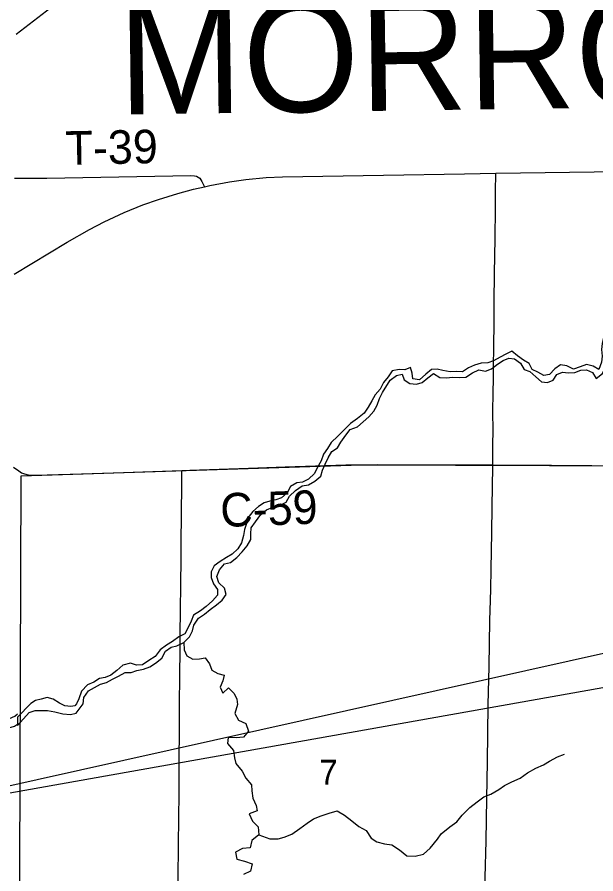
# Model space of a CAD drawing. Extents: x 0 to 45.9, y 0 to 22.
# Drawn here: x 5.48 to 6.459, y 18.033 to 19.483 of the extents above; entities that cross this region are included whole.
import ezdxf

# ---------------------------------------------------------------- set-up
doc = ezdxf.new("R2010")
doc.units = 0
for name, color, linetype in [('GM_X_County_Road', 7, 'Continuous'), ('GM_X_County_Road_Text', 7, 'Continuous'), ('GM_X_County_Text', 7, 'Continuous'), ('GM_X_Minor_River', 7, 'Continuous'), ('GM_X_Rail_Line', 7, 'Continuous'), ('GM_X_Section', 7, 'Continuous'), ('GM_X_Section_Text', 7, 'Continuous'), ('GM_X_State_Route', 7, 'Continuous'), ('GM_X_Township_Road', 7, 'Continuous'), ('GM_X_Township_Road_Text', 7, 'Continuous'), ('SH_Border', 7, 'Continuous')]:
    doc.layers.add(name, color=color, linetype=linetype)

msp = doc.modelspace()

# ---------------------------------------------------------------- linework, layer by layer
at = {"layer": 'GM_X_County_Road'}
for points in [[(5.474, 18.721), (5.4831, 18.7146), (5.4878, 18.7117), (5.4926, 18.7095), (5.4991, 18.7082), (5.5114, 18.7076), (5.589, 18.71), (5.6605, 18.7123), (5.7587, 18.7155)], [(5.7587, 18.7155), (5.7723, 18.716), (5.8717, 18.7194), (5.9338, 18.7219), (6.0363, 18.7249), (6.0892, 18.7256), (6.1824, 18.7251), (6.2384, 18.725), (6.2851, 18.7249)], [(6.2851, 18.7249), (6.3844, 18.7247), (6.5212, 18.7234), (6.6051, 18.7221), (6.7354, 18.7198), (6.8535, 18.7178), (6.9374, 18.7166), (6.9747, 18.7162), (7.012, 18.7157), (7.0772, 18.7145), (7.1611, 18.7135), (7.2295, 18.7125), (7.2979, 18.7112), (7.4129, 18.7096), (7.5589, 18.7064), (7.5646, 18.7065)]]:
    msp.add_lwpolyline(points, dxfattribs=at)
at = {"layer": 'GM_X_Minor_River'}
msp.add_line((5.4811, 18.298), (5.481, 18.2841), dxfattribs=at)
for points in [[(6.5218, 18.9995), (6.5179, 18.9939), (6.5138, 18.9842), (6.5041, 18.9742), (6.4944, 18.9672), (6.4847, 18.9599), (6.4758, 18.9503), (6.4721, 18.9405), (6.4699, 18.9303), (6.4689, 18.9201), (6.4701, 18.9087), (6.4687, 18.8988), (6.4642, 18.8864), (6.4545, 18.892), (6.4436, 18.8946), (6.4328, 18.8907), (6.4214, 18.8868), (6.4102, 18.8928)], [(6.4437, 18.8858), (6.4534, 18.881), (6.4596, 18.8713), (6.4704, 18.8794), (6.4749, 18.8899), (6.4755, 18.9005), (6.4747, 18.9108), (6.4749, 18.9203), (6.4764, 18.9309), (6.4801, 18.941), (6.4887, 18.9507), (6.4999, 18.9618), (6.5108, 18.9694), (6.5242, 18.9888), (6.5233, 18.9987), (6.5218, 18.9995)], [(6.4102, 18.8928), (6.3996, 18.8943), (6.39, 18.8877), (6.381, 18.8777), (6.3711, 18.8761), (6.3614, 18.8817), (6.3513, 18.8865), (6.3467, 18.8965), (6.3366, 18.9021), (6.3269, 18.9096), (6.3169, 18.9171), (6.3069, 18.9124), (6.2973, 18.907), (6.2862, 18.9008), (6.2766, 18.8977), (6.2652, 18.8972), (6.2542, 18.8937), (6.2438, 18.8891), (6.2338, 18.8825), (6.2228, 18.8832), (6.213, 18.8823), (6.2005, 18.8846), (6.1907, 18.8871), (6.1812, 18.8863), (6.1716, 18.8786), (6.1607, 18.869), (6.1494, 18.8704), (6.1485, 18.8803), (6.1457, 18.8899), (6.1362, 18.886), (6.1263, 18.8866), (6.1145, 18.8839), (6.1082, 18.8739), (6.1003, 18.8642), (6.0944, 18.853), (6.0858, 18.8433), (6.0802, 18.8336), (6.0742, 18.8228), (6.0671, 18.8127), (6.0563, 18.8035), (6.0443, 18.7947), (6.033, 18.7836), (6.0229, 18.7737), (6.0116, 18.763), (6.0056, 18.7529), (5.9985, 18.7428), (5.9948, 18.7319), (5.9877, 18.7199), (5.9832, 18.7102), (5.9731, 18.7006), (5.9631, 18.6959), (5.9533, 18.6947), (5.9429, 18.6881), (5.9373, 18.6777), (5.9276, 18.6692), (5.918, 18.666), (5.9077, 18.6637), (5.8982, 18.6605), (5.8885, 18.6547), (5.8788, 18.6462), (5.8714, 18.6358), (5.8681, 18.626), (5.8651, 18.6158), (5.8633, 18.6056), (5.86, 18.5932), (5.8536, 18.5827), (5.8439, 18.5739), (5.8343, 18.5684), (5.8235, 18.5612), (5.8138, 18.5542), (5.8086, 18.5437), (5.8083, 18.5342), (5.8126, 18.5238), (5.8195, 18.5142), (5.8192, 18.5043), (5.8106, 18.4947), (5.8002, 18.4851), (5.7905, 18.4781), (5.7789, 18.4705), (5.7745, 18.4607), (5.7689, 18.4487), (5.764, 18.439), (5.7541, 18.4339), (5.7432, 18.4263), (5.7332, 18.4201), (5.7224, 18.412), (5.7138, 18.4005), (5.7033, 18.3939), (5.6922, 18.3866), (5.6823, 18.3862), (5.6722, 18.3895), (5.6592, 18.3857), (5.6487, 18.3772), (5.639, 18.3691), (5.6295, 18.3652), (5.6199, 18.3632), (5.6099, 18.3574), (5.5996, 18.3528), (5.5891, 18.342), (5.5845, 18.3292), (5.581, 18.3207)], [(5.5922, 18.3207), (5.5933, 18.3313), (5.6012, 18.3425), (5.6212, 18.354), (5.6315, 18.3564), (5.6415, 18.3622), (5.6515, 18.3676), (5.663, 18.3738), (5.6732, 18.3735), (5.6828, 18.3767), (5.6938, 18.379), (5.7046, 18.3833), (5.7142, 18.3895), (5.725, 18.3979), (5.731, 18.4095), (5.7407, 18.4164), (5.7506, 18.4185), (5.7621, 18.4242), (5.7719, 18.4338), (5.7771, 18.4439), (5.7792, 18.4537), (5.7871, 18.4653), (5.7972, 18.4722), (5.8068, 18.4803), (5.8173, 18.488), (5.827, 18.4957), (5.834, 18.5054), (5.8313, 18.5161), (5.8217, 18.5251), (5.8179, 18.5362), (5.8227, 18.5471), (5.8313, 18.5575), (5.8412, 18.5599), (5.8517, 18.568), (5.861, 18.5776), (5.8693, 18.588), (5.8756, 18.5988), (5.8755, 18.6083), (5.8762, 18.6182), (5.8837, 18.6286), (5.8927, 18.6409), (5.9024, 18.6486), (5.9127, 18.6536), (5.9238, 18.656), (5.9353, 18.6621), (5.9409, 18.6722), (5.9514, 18.6818), (5.9626, 18.6895), (5.9732, 18.6911), (5.984, 18.6976), (5.9941, 18.7061), (5.997, 18.7159), (6.0015, 18.7264), (6.0067, 18.7369), (6.0127, 18.7474), (6.0223, 18.7535), (6.0279, 18.7636), (6.0365, 18.7752), (6.0436, 18.7849), (6.0559, 18.7895), (6.0656, 18.7975), (6.0753, 18.8064), (6.0839, 18.816), (6.0891, 18.8258), (6.0935, 18.8374), (6.0984, 18.8472), (6.1111, 18.8681), (6.1223, 18.8761), (6.1318, 18.8785), (6.1349, 18.8689), (6.1446, 18.8626), (6.1559, 18.8615), (6.1655, 18.8643), (6.1752, 18.872), (6.1848, 18.8797), (6.1956, 18.8729), (6.2059, 18.8723), (6.2172, 18.8731), (6.2282, 18.8728), (6.2392, 18.8736), (6.2508, 18.8805), (6.2615, 18.8856), (6.2724, 18.8834), (6.2828, 18.8876), (6.2928, 18.8953), (6.3025, 18.9015), (6.3121, 18.9058), (6.3219, 18.9044), (6.3319, 18.8973), (6.338, 18.8861), (6.3478, 18.8832), (6.3578, 18.8738), (6.3674, 18.8655), (6.3772, 18.8641), (6.3868, 18.8684), (6.3935, 18.8781), (6.4031, 18.882), (6.4132, 18.8806), (6.4239, 18.8811), (6.4338, 18.8853), (6.4437, 18.8858)], [(5.7621, 18.4242), (5.7629, 18.4117), (5.7676, 18.4016), (5.7773, 18.3961), (5.789, 18.3965), (5.7985, 18.3985), (5.8058, 18.3884), (5.8097, 18.3773), (5.8198, 18.3721), (5.8303, 18.3691), (5.8281, 18.3593), (5.824, 18.3488), (5.8283, 18.3388), (5.838, 18.3476), (5.8476, 18.3379), (5.8519, 18.3283), (5.853, 18.3194)], [(5.5533, 18.3209), (5.5521, 18.3218), (5.5413, 18.3285), (5.5312, 18.3311), (5.5209, 18.3287), (5.5114, 18.3263), (5.5037, 18.3211)], [(5.4235, 18.318), (5.4237, 18.304), (5.4266, 18.2914), (5.4386, 18.2818), (5.451, 18.2786), (5.4624, 18.2788), (5.4758, 18.2828), (5.481, 18.2863)], [(5.4371, 18.3125), (5.4404, 18.303), (5.4497, 18.2926), (5.4622, 18.2932), (5.4764, 18.2995), (5.4811, 18.3039)], [(5.481, 18.2841), (5.5005, 18.3059), (5.5108, 18.309), (5.5222, 18.3094), (5.5316, 18.3094), (5.5438, 18.3072), (5.5575, 18.3038), (5.5704, 18.3024), (5.5802, 18.3047), (5.5922, 18.3207)], [(5.5037, 18.3211), (5.4811, 18.298)], [(5.581, 18.3207), (5.578, 18.3172), (5.5709, 18.3158), (5.5608, 18.3169), (5.5533, 18.3209)], [(5.853, 18.3194), (5.8484, 18.304), (5.8545, 18.2931), (5.8674, 18.2874), (5.8717, 18.2742), (5.8633, 18.2639), (5.8508, 18.2631), (5.8372, 18.2638), (5.8361, 18.2532), (5.8464, 18.2415), (5.8479, 18.229), (5.8502, 18.2195), (5.8609, 18.2066), (5.8674, 18.1949), (5.8769, 18.1832), (5.8773, 18.1733), (5.8789, 18.1608), (5.8846, 18.1487), (5.8866, 18.1392), (5.8729, 18.1346), (5.8783, 18.1217), (5.8882, 18.1123), (5.889, 18.0986), (5.8776, 18.0891), (5.8746, 18.077), (5.8614, 18.0758), (5.8496, 18.0693), (5.8519, 18.0579), (5.8648, 18.0542), (5.8781, 18.0497), (5.8752, 18.0375), (5.863, 18.0318)], [(5.889, 18.0986), (5.908, 18.0919), (5.922, 18.0919), (5.9318, 18.095), (5.9451, 18.1), (5.9584, 18.1095), (5.9712, 18.1186), (5.9814, 18.1262), (5.9947, 18.1308), (6.0083, 18.1354), (6.0216, 18.1397), (6.0338, 18.1321), (6.0463, 18.1227), (6.0581, 18.1132), (6.071, 18.1061), (6.079, 18.0932), (6.0886, 18.0868), (6.1015, 18.0834), (6.1144, 18.0819), (6.1269, 18.0736), (6.1398, 18.0634), (6.1535, 18.0627), (6.1679, 18.0662), (6.1789, 18.0761), (6.1913, 18.0913), (6.1978, 18.1008), (6.2125, 18.1122), (6.2242, 18.1206), (6.2333, 18.1324), (6.2462, 18.145), (6.2586, 18.1549), (6.2696, 18.1629), (6.2817, 18.1678), (6.295, 18.1755), (6.3048, 18.1823), (6.3173, 18.1888), (6.331, 18.1949), (6.3438, 18.2037), (6.3575, 18.2117), (6.3707, 18.2175), (6.3809, 18.2236), (6.3942, 18.2308), (6.4063, 18.2354)]]:
    msp.add_lwpolyline(points, dxfattribs=at)
at = {"layer": 'GM_X_Rail_Line'}
msp.add_line((5.4785, 19.4538), (5.8183, 19.7169), dxfattribs=at)
at = {"layer": 'GM_X_Section'}
msp.add_lwpolyline([(5.4871, 18.7066), (6.0626, 18.725), (6.54, 18.7231), (6.5217, 17.7114), (6.0871, 17.7131), (5.4835, 17.7031)], close=True, dxfattribs=at)
at = {"layer": 'GM_X_State_Route'}
msp.add_lwpolyline([(5.4755, 19.0477), (5.5651, 19.1016), (5.6028, 19.1233), (5.6276, 19.1361), (5.6614, 19.1518), (5.693, 19.1648), (5.7193, 19.1742), (5.7519, 19.1843), (5.7789, 19.1917), (5.7973, 19.1957), (5.8061, 19.1977), (5.8397, 19.2039), (5.8674, 19.2077), (5.9014, 19.211), (5.9293, 19.2124), (6.1002, 19.2155), (6.2369, 19.2176), (6.2899, 19.2184), (6.498, 19.2217)], dxfattribs=at)
at = {"layer": 'GM_X_Township_Road'}
for points in [[(5.4761, 19.2103), (5.5306, 19.2101), (5.7742, 19.2147), (5.7805, 19.2142), (5.7836, 19.2134), (5.7866, 19.212), (5.7892, 19.2099), (5.7913, 19.2073), (5.7928, 19.2044), (5.7973, 19.1957)], [(6.2851, 18.7249), (6.2852, 18.7472), (6.2852, 18.7627), (6.2853, 18.7791), (6.2851, 18.8184), (6.2855, 18.8432), (6.2861, 18.8746), (6.2862, 18.8987), (6.2866, 18.9168), (6.2869, 18.9327), (6.2873, 18.9579), (6.2874, 18.9768), (6.2875, 19.0141), (6.2878, 19.0358), (6.288, 19.0544), (6.2882, 19.073), (6.2887, 19.1134), (6.2894, 19.1538), (6.2897, 19.1941), (6.2898, 19.2115), (6.2899, 19.2184)], [(6.2815, 18.5146), (6.2824, 18.5485), (6.2835, 18.6106), (6.284, 18.654), (6.285, 18.7224), (6.2851, 18.7249)], [(5.7497, 17.7112), (5.75, 17.7565), (5.7507, 17.8653), (5.7509, 17.915), (5.7514, 17.9398), (5.7522, 17.9709), (5.7527, 18.0268), (5.7534, 18.0796), (5.754, 18.1293), (5.7544, 18.1666), (5.7545, 18.2288), (5.7549, 18.2723), (5.755, 18.3251), (5.7556, 18.3624), (5.7563, 18.4183), (5.7563, 18.4431), (5.7567, 18.4742), (5.7573, 18.527), (5.7577, 18.5612), (5.7579, 18.6016), (5.7582, 18.6327), (5.7587, 18.701), (5.7587, 18.7103), (5.7587, 18.7155)], [(6.2684, 17.7593), (6.2691, 17.8188), (6.2699, 17.8653), (6.2704, 17.9026), (6.2713, 17.9647), (6.2723, 18.0268), (6.2736, 18.0889), (6.2747, 18.1603), (6.2757, 18.2224), (6.2773, 18.3187), (6.2787, 18.3839), (6.2801, 18.4615), (6.281, 18.4957), (6.2815, 18.5146)]]:
    msp.add_lwpolyline(points, dxfattribs=at)
at = {"layer": 'SH_Border'}
msp.add_lwpolyline([(9.5057, 19.0827), (5.2104, 18.1241), (9.5057, 18.8875)], close=True, dxfattribs=at)

# ---------------------------------------------------------------- texts
at = {"layer": 'GM_X_County_Road_Text'}
msp.add_text('C-59', height=0.05682, rotation=2.0669, dxfattribs=at).set_placement((5.8249, 18.6197))
at = {"layer": 'GM_X_County_Text'}
msp.add_text('MORROW COUNTY', height=0.189394, rotation=0.8203, dxfattribs=at).set_placement((5.6522, 19.3177))
at = {"layer": 'GM_X_Section_Text'}
msp.add_text('7', height=0.0419, rotation=0, dxfattribs=at).set_placement((5.9914, 18.1839))
at = {"layer": 'GM_X_Township_Road_Text'}
msp.add_text('T-39', height=0.05682, rotation=1.0729, dxfattribs=at).set_placement((5.5625, 19.2327))

doc.saveas('drawing.dxf')
